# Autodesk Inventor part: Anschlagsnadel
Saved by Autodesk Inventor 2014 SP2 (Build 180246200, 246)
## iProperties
Created: 2015-07
Part Number: Anschlagsnadel
Material: Generisch
Document SubType Name: Modeling
Designer: e_krauts
Density: 1 g/cm^3
Appearance: Vorgabe
Mass: 5.7425 g
Surface Area: 38.8263 cm^2
Volume: 5.7425 cm^3
Sending System: SolidWorks 2011
Last Author: e_boekem
Sachnummer: NWS 100-00-07
Erstellt durch: XYZ
Werkstoff: 10SPb20
Einheit: Stck.
Author: e_krauts
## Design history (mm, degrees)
node "Anschlagsnadel.ipt1"
node "Rotation1"
node "Basis1"
